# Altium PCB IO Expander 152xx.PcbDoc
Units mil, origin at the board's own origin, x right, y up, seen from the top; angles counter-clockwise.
Board outline 1025 x 2250 mil, 2 copper layers (Top Layer, Bottom Layer), stack 61.811 mil thick; 39 components, 39 nets, 131 pads, 30 vias.
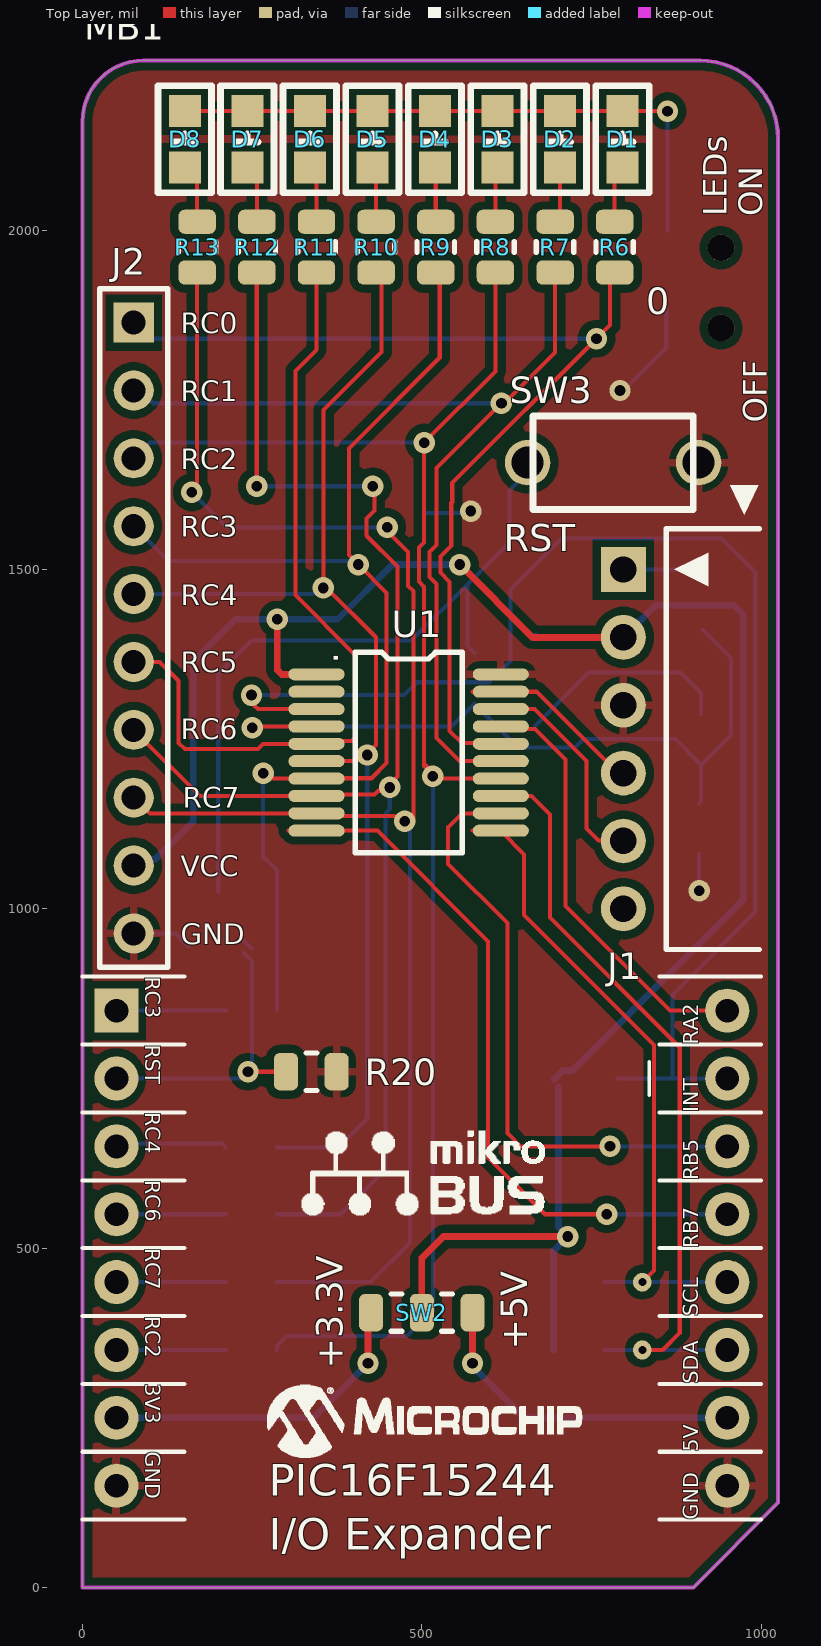
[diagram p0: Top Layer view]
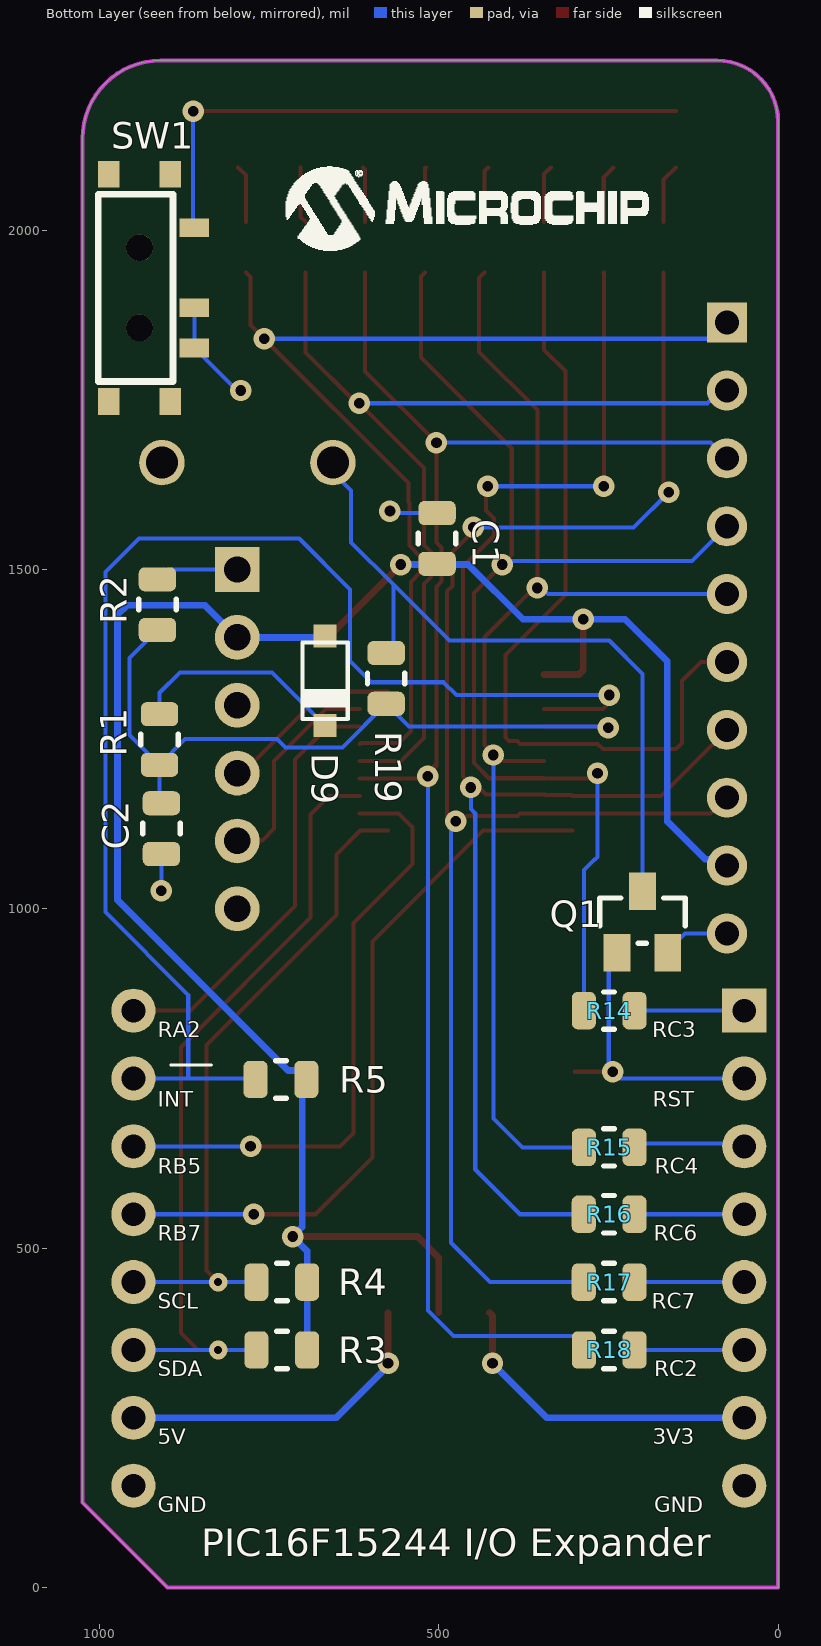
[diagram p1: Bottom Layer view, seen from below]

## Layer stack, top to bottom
Top Solder: solder mask 0.3937, Solder Resist, Dk 3.5
Top Layer: signal copper 1.378
Dielectric1: core 59.0551, FR-4, Dk 4.8
Bottom Layer: signal copper 1.378
Bottom Solder: solder mask 0.3937, Solder Resist, Dk 3.5

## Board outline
0,0 0,2160 cw(c90,2160) 90,2250 910,2250 cw(c910,2135) 1025,2135 1025,125 900,0

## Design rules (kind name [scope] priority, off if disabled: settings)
AcuteAngle [All] p1: minimum=0.00000000000000E+0000 checktracksonly=TRUE
BoardOutlineClearance BoardOutlineClearance_Overlay [OnLayer('Top Overlay','Bottom Overlay')] p1: gap=0 ignorepadtopadclearanceinfootprint=FALSE
BoardOutlineClearance [All] p2: gap=15 ignorepadtopadclearanceinfootprint=FALSE
Clearance "Net to Polygon 0.5mm" [InNet('your net here') vs (IsRegion)] p1: gap=19.68 ignorepadtopadclearanceinfootprint=FALSE
Clearance "Poly 0.3mm" [(IsRegion)] p2: gap=11.81 ignorepadtopadclearanceinfootprint=FALSE
Clearance [All] p3: gap=9.84 ignorepadtopadclearanceinfootprint=TRUE
ComponentClearance ComponentClearance_ignore [HasFootprint('NET_TIE_0.5mm')] p1: gap=0 collisioncheckmode=3 verticalgap=0 showdistances=FALSE
ComponentClearance [All] p2: gap=7.87 collisioncheckmode=3 verticalgap=7.87 showdistances=FALSE
DiffPairsRouting [All] p1: maxlimit=9.84 minlimit=9.84 mostfreqgap=9.84 toplayer_minwidth=9.84 toplayer_maxwidth=9.84 toplayer_prefwidth=9.84 bottomlayer_minwidth=9.84 bottomlayer_maxwidth=9.84 bottomlayer_prefwidth=9.84 maxuncoupledlength=500
FabricationTestPointUsage TestPointUsage [All] p1: valid=0 allowmultiple=FALSE
FabricationTestpoint Testpoint [All] p1: side=3 testpointundercomponent=TRUE minsize=40 maxsize=100 preferedsize=60 minholesize=0 maxholesize=40 preferedholesize=32 testpointgrid=1 allowsidetop=TRUE allowsidebottom=TRUE usegrid=TRUE gridtolerance=0.01
HoleSize [All] p1: absolutevalues=TRUE maxlimit=236.22 minlimit=9.84 maxpercent=80.000 minpercent=20.000
HoleToHoleClearance [All] p1: gap=11.81 allowstackedmicrovias=FALSE
MinimumAnnularRing [All] p1: minimumring=5.91
MinimumSolderMaskSliver [All] p1: minsoldermaskwidth=1
PasteMaskExpansion PasteMaskExpansion_DNP [IsPad AND HasCompParameterValue('Populated','DNP')] p1: expansion=-196.85
PasteMaskExpansion [All] p2: expansion=0
PlaneClearance PlaneClearance_pads [IsPad] p1: clearance=11.81
PlaneClearance PlaneClearance_drill [IsObjectKind('Hole')] p2: clearance=15.75
PlaneConnect PlaneConnect_full [IsVia] p1: planeconnectstyle=Direct reliefexpansion=19.68 reliefentries=4 reliefconductorwidth=11.81 reliefairgap=11.81
PlaneConnect [All] p2: planeconnectstyle=Relief reliefexpansion=11.81 reliefentries=4 reliefconductorwidth=9.84 reliefairgap=9.84
PolygonConnect PolygonConnect_0.7 [IsNamedPolygon('0.7mm') vs (InPadClass('All Pads'))] p1: connectstyle=Relief reliefconductorwidth=27.56 reliefentries=4 polygonreliefangle="90 Angle" airgapwidth=9.84
PolygonConnect PolygonConnect_0.5 [IsNamedPolygon('0.5mm') vs (InPadClass('All Pads'))] p2: connectstyle=Relief reliefconductorwidth=19.68 reliefentries=4 polygonreliefangle="90 Angle" airgapwidth=9.84
PolygonConnect PolygonConnect_full [All vs IsVia or IsNamedPolygon('full')] p3: connectstyle=Direct reliefconductorwidth=0 reliefentries=4 polygonreliefangle="90 Angle" airgapwidth=10
PolygonConnect [All] p4: connectstyle=Relief reliefconductorwidth=11.81 reliefentries=4 polygonreliefangle="90 Angle" airgapwidth=9.84
RoutingCorners [All] p1: cornerstyle=45-Degree minsetback=98.43 maxsetback=98.43
RoutingVias [All] p1: holewidth=15.75 width=31.5 viastyle="Through Hole" minholewidth=11.81 minwidth=27.56 maxholewidth=62.99 maxwidth=98.43
SMDToCorner [All] p1: distance=39370
ShortCircuit [IsNet] p1: allowed=FALSE
SilkToSilkClearance [All] p1: silktosilkclearance=5
SilkToSolderMaskClearance SilkscreenOverComponentPads [IsPad] p1: minsilkscreentomaskgap=3 clearancetoexposedcopper=TRUE
SolderMaskExpansion SolderMaskExpansion_Component_Via [IsComponentVia] p1: expansion=2.95 istentingtop=FALSE soldermaskfromhole=TRUE
SolderMaskExpansion [All] p2: expansion=3.94 istentingtop=FALSE
UnRoutedNet [All] p1: checkbadconnections=TRUE
ViasUnderSMD [All] p1: allowed=FALSE
Width [All] p1: maxlimit=10 minlimit=6 preferedwidth=6 minimp=50.000000 maximp=50.000000 favimp=50.000000
15 further rules are at their usual default settings.

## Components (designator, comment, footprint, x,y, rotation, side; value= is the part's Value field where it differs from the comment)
C1 "Capacitor NP" RES_C_0805 502.52,1545.77 r270 bottom value=0.1uF
C2 "Capacitor NP" RES_C_0805 908.71,1118.16 r90 bottom value=10nF
D1 "LED" "0805 LED Package" 795.59,2133.94 r90 top
D2 "LED" "0805 LED Package" 703.48,2133.94 r90 top
D3 "LED" "0805 LED Package" 611.36,2133.94 r90 top
D4 "LED" "0805 LED Package" 519.25,2133.94 r90 top
D5 "LED" "0805 LED Package" 427.14,2133.94 r90 top
D6 "LED" "0805 LED Package" 335.03,2133.94 r90 top
D7 "LED" "0805 LED Package" 242.92,2133.94 r90 top
D8 "LED" "0805 LED Package" 150.81,2133.94 r90 top
D9 "SD101BW-E3-08" SOD123 667.62,1336.09 r270 bottom
J1 "Header 1x6" HDR_F_2.54_1x6_RA 797,1250 r270 top locked value="HDR-2.54 Female 1x6"
J2 "Header 10" HDR1X10 75.49,1863.74 r270 top (schematic designator P?)
MB1 "mikroBUS" "mikroBUS - Large" 0,0 r0 top locked
Q1 "Transistor MOS-N GSD" SOT-23-3 200,980.61 r180 bottom value=2N7002
R1 "Resistor" RES_C_0805 911.5,1249.54 r90 bottom value=10k
R2 "Resistor" RES_C_0805 914.54,1448.18 r90 bottom value=470R
R3 "Resistor" RES_C_0805 731.31,350 r180 bottom value=DNP
R4 "Resistor" RES_C_0805 731.31,450 r180 bottom value=DNP
R5 "Resistor" RES_C_0805 732.63,748.6 r180 bottom value=10k
R6 "Resistor" RES_C_0805 784.19,1975 r90 top value=1k
R7 "Resistor" RES_C_0805 696.31,1975 r90 top value=1k
R8 "Resistor" RES_C_0805 608.43,1975 r90 top value=1k
R9 "Resistor" RES_C_0805 520.55,1975 r90 top value=1k
R10 "Resistor" RES_C_0805 432.67,1975 r270 top value=1k
R11 "Resistor" RES_C_0805 344.79,1975 r270 top value=1k
R12 "Resistor" RES_C_0805 256.91,1975 r270 top value=1k
R13 "Resistor" RES_C_0805 169.03,1975 r270 top value=1k
R14 "Resistor" RES_C_0805 248.95,850 r0 bottom value=DNP
R15 "Resistor" RES_C_0805 248.95,648.62 r0 bottom value=DNP
R16 "Resistor" RES_C_0805 249,550 r0 bottom value=DNP
R17 "Resistor" RES_C_0805 249,450 r0 bottom value=DNP
R18 "Resistor" RES_C_0805 248.95,350 r0 bottom value=DNP
R19 "Resistor" RES_C_0805 577.47,1339.57 r90 bottom value=1k
R20 "Resistor" RES_C_0805 337.21,760 r180 top value=10k
SW1 "SWITCH SLIDE 3 Pin SPDT" PCBComponent_1 940.85,1915 r90 bottom locked
SW2 "SMD Power Select" "3-Pad Select 0805" 462.6,405 r0 top
SW3 "SPST Switch" PTS636 781.97,1657.41 r0 top
U1 "PIC16F15244" SSOP-20_P0.65 480.62,1230.32 r0 top locked

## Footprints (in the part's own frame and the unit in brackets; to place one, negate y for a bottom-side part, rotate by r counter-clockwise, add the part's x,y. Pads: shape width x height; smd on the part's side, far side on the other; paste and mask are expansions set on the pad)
"3-Pad Select 0805" [mm] "Chip Resistor, 2-Leads, Body 2.0x1.3mm, IPC Medium Density"
  rrect50% 0.9x1.4 smd: 1(-0.95,0) 2(0.95,0) 3(2.85,0)
  silkscreen extent -0.2,-0.7 2.1,0.7, body extent -1,-0.63 2.6,0.63, height 0.78
"0805 LED Package" [mm] "0805 Package for LED"
  rect 1.2x1.2 smd: Anode(-1.05,0) Cathode(1.05,0)
  silkscreen extent -2,-1 2,1
HDR1X10 [mm] "Connector; Header; 10 Position"
  rect 1.5x1.5 hole 0.9: 1(0,0)
  round 1.5 hole 0.9: 2(2.54,0) 3(5.08,0) 4(7.62,0) 5(10.16,0) 6(12.7,0) 7(15.24,0) 8(17.78,0) 9(20.32,0) 10(22.86,0)
  silkscreen extent -1.27,-1.27 24.13,1.27
HDR_F_2.54_1x6_RA [mil] "Header Female Right Angle 6 Way 2.54mm Pitch"
  rect 66x66 hole 39: 1(-250,0)
  round 66 hole 39: 2(-150,0) 3(-50,0) 4(50,0) 5(150,0) 6(250,0)
  silkscreen extent -310,63 310,200, body extent -310,-8 310,395, height 97
"mikroBUS - Large" [mil]
  rect 65x65 hole 35: 1(50,850)
  round 65 hole 35: 2(50,750) 3(50,650) 4(50,550) 5(50,450) 6(50,350) 7(50,250) 8(50,150) 9(950,150) 10(950,250) 11(950,350) 12(950,450) 13(950,550) 14(950,650) 15(950,750) 16(950,850)
  Keep-Out Layer lines w6: 910,2250 90,2250 ccw(c90,2160) 0,2160 0,0 900,0 1025,125 1025,2135
  silkscreen extent 0,100 1000,900, body extent -5,100 1010,900, height 82
PCBComponent_1 [mm]
  rect 0.7x1.1 smd: 1(2.25,-2.05) 2(-0.75,-2.05) 3(-2.25,-2.05)
  round 1 hole 1 unplated: MECH-1(-1.5,0) MECH-2(1.5,0)
  rect 1x0.8 smd: MECH-3(4.25,1.15) MECH-4(4.25,-1.15) MECH-5(-4.25,-1.15) MECH-6(-4.25,1.15)
  silkscreen extent -3.5,-1.25 3.5,1.55
PTS636 [mil] "PTS636 TH Switch, 6mm x 3.5mm, 4.5mm Tall"
  round 67 hole 47.24: 1(-125.98,0) 2(125.98,0)
  silkscreen extent -118,-69 118,69
RES_C_0805 [mm] "Chip Resistor, 2-Leads, Body 2.0x1.3mm, IPC Medium Density"
  rrect50% 0.9x1.4 smd: 1(-0.95,0) 2(0.95,0)
  silkscreen extent -0.2,-0.7 0.2,0.7, body extent -1,-0.63 1,0.63, height 0.78
SOD123 [mm]
  rect 0.85x0.85 smd: ANODE(-1.675,0) CATHODE(1.675,0)
  silkscreen extent -1.43,-0.85 1.43,0.85
SOT-23-3 [mm]
  rect 1x1.4 smd: 1(-0.95,-1.15) 2(0.95,-1.15) 3(0,1.15)
  silkscreen extent -1.6,-0.8 1.6,0.9, body extent -1.5,-1.25 1.5,1.25, height 1.09
SSOP-20_P0.65 [mm] "SOP, 20-Leads, Body 7.5x5.6mm (max), Pitch 0.65mm, IPC Medium Density"
  oval 2.1x0.45 smd mask+0.05: 1(-3.45,2.925) 2(-3.45,2.275) 3(-3.45,1.625) 4(-3.45,0.975) 5(-3.45,0.325) 6(-3.45,-0.325) 7(-3.45,-0.975) 8(-3.45,-1.625) 9(-3.45,-2.275) 10(-3.45,-2.925) 11(3.45,-2.925) 12(3.45,-2.275) 13(3.45,-1.625) 14(3.45,-0.975) 15(3.45,-0.325) 16(3.45,0.325) 17(3.45,0.975) 18(3.45,1.625) 19(3.45,2.275) 20(3.45,2.925)
  silkscreen extent -2,-3.75 2,3.75, body extent -3.95,-3.65 3.95,3.67, height 1.95

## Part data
C1 C2: library part CAP2000, Package=0805, Voltage=10V
D9: library part SC_Diode, "Schottky Diode"
J1: library part CON0170, Current=3A, Manufacturer 1=Sullins, Manufacturer 2=Mill-Max, Manufacturer 3="SHENZHEN JUNHAO ENGINEERING", Manufacturer 4=Samtec, Manufacturer Part Number 1=PPPC061LGBN-RC, Manufacturer Part Number 2=801-43-006-20-001000, Manufacturer Part Number 3=R-212-0620-0021-000, Manufacturer Part Number 4=SSW-106-02-F-S-RA, Supplier Part Number 1=S5481-ND
J2: "Header, 10-Pin"
MB1: library part "mikroBUS compatible add-on board", "mikroBUS compatible add-on board"
Q1: library part TRA1102, "Transistor MOS", Current=170mA, Drain to Source Voltage=60V, Gate to Source Voltage=20V, Manufacturer 1="Diodes Inc", Manufacturer Part Number 1=2N7002-7-F, Operating Temperature="-55C to +150C", Package=SOT-23-3, Power=370mW, Supplier Part Number 1=2N7002-FDICT-ND
R1 R20: library part RSMT0027, Package=0805, Tolerance=5%
R2 R6 R7 R8 R9 R10 R11 R12 R13 R14 R15 R16 R17 R18 R19: library part RSMT0097, Package=0805, Tolerance=5%
R3 R4 R5: library part RSMT0097, Package=0805, Tolerance=5%, Voltage=150V
SW2: library part "SWITCH SLIDE 3 Pin SPDT"
SW3: library part SPST
U1: library part "PIC16F1524X SOIC-20_SSOP-20_PDIP-20", "PIC16F1524X SOIC-20_SSOP-20_PDIP-20"

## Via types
v1: diameter 31.5, hole 15.75, Top Layer to Bottom Layer, 28 vias
v2: diameter 27.56, hole 11.81, Top Layer to Bottom Layer, 2 vias

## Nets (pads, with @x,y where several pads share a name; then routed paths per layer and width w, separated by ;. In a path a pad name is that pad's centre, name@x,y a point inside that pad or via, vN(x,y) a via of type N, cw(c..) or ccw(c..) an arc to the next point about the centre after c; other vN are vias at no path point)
+3.3: MB1.7 SW2.1 | length 480.6
  Top Layer w10: v1(420.78,330.32) 420.78,400.59 SW2.1
  Bottom Layer w10: MB1.7 340.47,250 v1(420.78,330.32)
+5: MB1.10 SW2.3 | length 492.6
  Top Layer w10: v1(574.73,330.32) 574.8,330.39 SW2.3 ; MB1.10@945,255 MB1.10
  Bottom Layer w10: v1(574.73,330.32) 574.73,326.48 651.2,250 MB1.10
\I\N\T\: MB1.15 R5.1 U1.3 | length 1990
  Top Layer w6: v1(248.95,1314.96) 253.83,1310.08 253.83,1298.77 258.31,1294.29 U1.3
  Bottom Layer w6: v1(248.95,1314.96) 474.02,1314.96 492.9,1333.83 599.29,1333.83 630.51,1365.05 630.51,1470.77 705.58,1545.84 941.9,1545.84 991.29,1496.45 991.29,995.43 869.2,873.34 869.2,750 ; 788.4,750 869.2,750 ; MB1.15 869.2,750
GND: C1.1 C2.1 J1.3 J2.10 MB1.8 MB1.9 Q1.2 R20.1 SW1.2 SW1.3 SW3.2 U1.20 | length 383.5
  Bottom Layer w6: J2.10 137.23,963.74 Q1.2@156.24,944.72 ; C1.1 569.11,1583.18 v1(571.99,1586.06) ; v1(792,1763.74) 797.46,1763.74 SW1.3 SW1.2 ; J1.3 J1.3@808.26,1288.74 ; v1@908.17,1025.89 v1(908.71,1026.42) C2.1
ICSPCLK: J1.5 U1.18 | length 319.4
  Top Layer w6: U1.18 666.28,1294.29 742.85,1217.73 742.85,1118.16 760.06,1100.94 796.06,1100.94 J1.5
ICSPDAT: J1.4 U1.19 | length 286.8
  Top Layer w6: 575.02,1319.88 U1.19 669.13,1319.88 789.01,1200 J1.4 J1.4@786.25,1210.75
NetC2_2: C2.2 R1.1 R2.1 R19.1 U1.4 | length 1126
  Top Layer w6: v1(250.27,1266.86) 252.11,1268.7 U1.4
  Bottom Layer w6: v1@242.27,1271.74 v1@250.27,1263.74 ; v1(250.27,1266.86) v1@250.27,1263.74 ; C2.2 911.5,1158.36 R1.1 ; R2.1 955.61,1369.72 955.61,1256.24 R1.1 ; v1@250.27,1263.74 255.25,1268.72 362.88,1268.72 544.02,1268.72 R19.1 641.97,1237.66 725.79,1237.66 738.13,1250 873.64,1250 R1.1
NetD1_Anode: D1.Anode R6.2 | length 84.9
  Top Layer w6: R6.2 784.19,2081.2 D1.Anode
NetD1_Cathode: D1.Cathode D2.Cathode D3.Cathode D4.Cathode D5.Cathode D6.Cathode D7.Cathode D8.Cathode SW1.1 | length 886.9
  Top Layer w6: D8.Cathode D7.Cathode D6.Cathode D5.Cathode D4.Cathode D3.Cathode D2.Cathode D1.Cathode v1(862,2175.28)
  Bottom Layer w6: SW1.1@862,1999.59 v1(862,2175.28)
NetD2_Anode: D2.Anode R7.2 | length 83.2
  Top Layer w6: R7.2 703.48,2019.57 D2.Anode
NetD3_Anode: D3.Anode R8.2 | length 81.4
  Top Layer w6: R8.2 608.43,2089.66 D3.Anode
NetD4_Anode: D4.Anode R9.2 | length 80.7
  Top Layer w6: D4.Anode 520.55,2091.3 R9.2
NetD5_Anode: D5.Anode R10.1 | length 82.5
  Top Layer w6: D5.Anode 432.67,2087.07 R10.1
NetD6_Anode: D6.Anode R11.1 | length 84.2
  Top Layer w6: D6.Anode 344.79,2082.84 R11.1
NetD7_Anode: D7.Anode R12.1 | length 86
  Top Layer w6: D7.Anode 256.91,2078.61 R12.1
NetD8_Anode: D8.Anode R13.1 | length 87.7
  Top Layer w6: D8.Anode 169.03,2074.37 R13.1
NetD9_Cathode: D9.CATHODE R1.2 | length 320.2
  Bottom Layer w6: D9.CATHODE 745.91,1348.43 881.46,1348.43 911.5,1318.38 R1.2
NetMB1_1: MB1.1 R14.1 | length 161.6
  Bottom Layer w6: MB1.1 R14.1
NetMB1_3: MB1.3 R15.1 | length 165.8
  Bottom Layer w6: MB1.3 54.38,654.38 205.79,654.38 R15.1
NetMB1_4: MB1.4 R16.1 | length 161.6
  Bottom Layer w6: MB1.4 R16.1
NetMB1_5: MB1.5 R17.1 | length 161.6
  Bottom Layer w6: MB1.5 R17.1
NetMB1_6: MB1.6 R18.1 | length 161.6
  Bottom Layer w6: MB1.6 R18.1
NetQ1_3: Q1.3 R19.2 SW3.1 | length 1063.5
  Bottom Layer w6: Q1.3 200,1346.23 248.83,1395.06 484.24,1395.06 566.99,1477.81 ; R19.2 566.99,1387.45 566.99,1477.81 ; SW3.1 655.98,1643.13 629.14,1616.28 629.14,1539.96 566.99,1477.81
RA2: MB1.16 U1.17 | length 633.4
  Top Layer w6: U1.17 652.09,1268.7 655.98,1264.81 666.55,1264.81 711.63,1219.73 711.63,1003.96 865.59,850 MB1.16
RB5: MB1.14 U1.12 | length 905.2
  Top Layer w6: U1.12 559.36,1140.75 538.77,1120.16 538.77,1066.02 625.97,978.82 625.97,669.37 645.34,650 v1(777.32,650)
  Bottom Layer w6: v1(777.32,650) MB1.14
RB7: MB1.13 U1.10 | length 1067.2
  Top Layer w6: 303.37,1115.16 U1.10 434.72,1115.16 597.78,952.1 597.78,633.82 681.59,550 v1(772.67,550)
  Bottom Layer w6: v1(772.67,550) MB1.13
RC0: J2.1 R6.1 U1.16 | length 1562.5
  Top Layer w6: U1.16 615.5,1244.06 558.91,1244.06 541.08,1261.88 541.08,1481.71 527.39,1495.4 527.39,1519.08 543.4,1535.09 543.4,1597.91 544.8,1599.3 544.8,1627.48 v1(757.32,1840) 777.32,1860 777.32,1930.72 R6.1
  Bottom Layer w6: J2.1 99.23,1840 v1(757.32,1840)
RC1: J2.2 R7.1 U1.15 | length 1427.6
  Top Layer w6: U1.15 616.36,1217.6 555.79,1217.6 521.77,1251.61 521.77,1478.61 511.55,1488.84 511.55,1525.65 521.77,1535.87 521.77,1649.49 v1(617.28,1745) 621.62,1745 696.31,1819.69 R7.1
  Bottom Layer w6: J2.2 85.35,1763.74 104.08,1745 v1(617.28,1745)
RC2: J2.3 R8.1 R18.2 U1.14 | length 2401.9
  Top Layer w6: 503.45,1214.41 503.45,1210.43 516.2,1197.68 v1(516.2,1195.34) ; 503.45,1474.53 495.71,1482.27 495.71,1532.21 503.5,1540 v1(503.5,1686.91) 608.43,1791.83 R8.1 ; 503.5,1474.48 503.5,1214.41 525.98,1191.93 U1.14
  Bottom Layer w6: J2.3 76.48,1663.74 99.65,1686.91 v1(503.5,1686.91) ; R18.2 286.36,356.25 300.63,370.52 478.37,370.52 516.2,408.36 v1(516.2,1195.34)
RC3: J2.4 R9.1 R14.2 U1.7 | length 1711.6
  Top Layer w6: v1(266.19,1200) 273.09,1200 281.15,1191.94 U1.7 ; U1.7@344.79,1192.41 425.86,1192.41 448.18,1214.73 448.18,1465.55 v1(406.49,1507.24) 392.49,1521.24 392.49,1678.17 526.4,1812.08 526.4,1931.75 R9.1
  Bottom Layer w6: J2.4 126.73,1512.5 395.37,1512.5 400.63,1507.24 v1(406.49,1507.24) ; v1(266.19,1200) 266.19,1076.35 269.7,1072.83 270.48,1072.83 286.36,1056.95 R14.2
RC4: J2.5 R10.2 R15.2 U1.6 | length 1837.9
  Top Layer w6: U1.6 403.63,1217.52 412.69,1226.58 v1(419.59,1226.58) 419.59,1228.92 432.34,1241.67 432.34,1400.15 359.65,1472.83 v1(354.87,1472.83) 354.87,1734.76 440.71,1820.6 440.71,1929.56 R10.2
  Bottom Layer w6: J2.5 338.87,1463.74 347.97,1472.83 v1(354.87,1472.83) ; R15.2 376.85,648.62 419.59,691.36 v1(419.59,1226.58)
RC5: J2.6 R11.2 U1.5 | length 1174.9
  Top Layer w6: J2.6 113.82,1363.74 141.47,1336.09 141.47,1244.57 150.81,1235.24 258.31,1235.24 266.19,1243.11 U1.5 380.44,1243.11 384.33,1247 396.3,1247 401.88,1252.58 401.88,1374.28 313.57,1462.59 313.57,1792.53 344.79,1823.75 R11.2
RC6: J2.7 R12.2 R16.2 U1.8 | length 2134.8
  Top Layer w6: J2.7 172.89,1166.34 303.37,1166.34 304.87,1167.85 342.92,1167.85 343.38,1168.31 430.32,1168.31 436.04,1174.04 447.91,1174.04 v1(452.79,1178.91) ; v1(256.83,1622.61) 256.83,1937.52 R12.2 ; v1(427.82,1622.61) 430.42,1620.01 430.42,1586.9 418.52,1575.01 418.52,1549.73 464.02,1504.23 464.02,1195.18 452.79,1183.95 v1@452.79,1179.07
  Bottom Layer w6: v1(256.83,1622.61) v1(427.82,1622.61) ; R16.2 380.36,550 446.27,615.92 446.27,1140.71 452.79,1147.23 v1(452.79,1178.91)
RC7: J2.8 R13.2 R17.2 U1.9 | length 2356.9
  Top Layer w6: J2.8 76.84,1163.74 99.83,1140.75 U1.9 380.44,1140.75 384.33,1136.86 459.97,1136.86 467.96,1128.87 v1(474.86,1128.87) 487.61,1128.87 487.61,1467.97 479.86,1475.71 479.86,1525.77 449.03,1556.6 v1(449.03,1562.37) ; v1(161.15,1613.62) 161.15,1619.48 169.03,1627.36 R13.2
  Bottom Layer w6: v1(161.15,1613.62) 213.18,1561.59 448.26,1561.59 v1(449.03,1562.37) ; R17.2 424.28,450 482.28,508 482.28,1114.55 474.86,1121.97 v1(474.86,1128.87)
RST: MB1.2 Q1.1 R20.2 | length 452.2
  Top Layer w6: v1(243.88,760) R20.2
  Bottom Layer w6: MB1.2 233.88,750 v1(243.88,760) 249.54,765.66 249.54,923.2 Q1.1 ; Q1.1@237.94,952.6 Q1.1@248.95,941.59
SCL: MB1.12 R4.1 U1.11 | length 987.9
  Top Layer w6: 575.02,1115.16 615.72,1115.16 650.62,1080.26 650.62,990.7 842,799.31 842,467 v2(825,450)
  Bottom Layer w6: R4.1 v2(825,450) MB1.12
SDA: MB1.11 R3.1 U1.13 | length 1173.8
  Top Layer w6: U1.13 661.89,1166.34 688.96,1139.27 688.96,987.09 880,796.05 880,375 855,350 v2(825,350)
  Bottom Layer w6: R3.1 v2(825,350) MB1.11
VCC: C1.2 D9.ANODE J1.2 J2.9 R3.2 R4.2 R5.2 SW2.2 U1.1 | length 3073.9
  Top Layer w10: v1(287.08,1426.69) 287.08,1352 293.61,1345.47 U1.1 ; SW2.2 500,485.43 531.65,517.08 v1(715,517.08) ; v1(555.98,1507.24) 663.22,1400 J1.2
  Bottom Layer w10: J2.9 84.91,1073.15 107.58,1073.15 163.22,1128.8 163.22,1364.37 225.54,1426.69 292.9,1426.69 376.15,1426.69 456.7,1507.24 v1(555.98,1507.24) ; D9.ANODE 669.66,1400 J1.2 844.24,1447.24 959.63,1447.24 973.45,1433.42 973.45,1013.09 722.09,761.73 707.65,761.73 695.23,749.31 R5.2 ; R3.2 R4.2 693.91,495.99 v1(715,517.08) 715,517.51 701.29,531.21 R5.2@701.29,737.7
VPP/\M\C\L\R\: J1.1 R2.2 | length 142.4
  Bottom Layer w6: J1.1@783.61,1486.61 J1.1 900.12,1500 R2.2
pads on no net: J1.6 SW1.MECH-1 SW1.MECH-2 SW1.MECH-3 SW1.MECH-4 SW1.MECH-5 SW1.MECH-6 U1.2

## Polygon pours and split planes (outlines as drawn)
GND on Top Layer "GND_L01_P002" (solid, remove dead copper, pour order 2): 1000,300 1000,0 0,0 0,300
GND on Top Layer "GND_L01_P004" (solid, remove dead copper, pour order 4): 0,0 416.11,0 416.11,2248.11 418,2250 0,2250
GND on Top Layer "GND_L01_P007" (solid, remove dead copper, pour order 7): -5,2249.05 -5,5 0,0 1030,0 1030,2249.05
no net on Top Overlay "NONET_L-01_P-001" (solid): 954.68,1623.91 995.46,1623.91 974.88,1580.61

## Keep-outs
Keep-Out Layer:
  lines w6: 910,2250 cw(c910,2135) 1025,2135 ; 1555,4120 cw(c1555,4005) 1670,4005
  text "'.Layer_Name'" at 11841.34,-6245 h59.06

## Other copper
Top Layer:
  text "'.ProjectRevisionART'" at 13226.29,-6238 h59.06
  text "'.Layer_Name'" at 11841.34,-6245 h59.06
Bottom Layer:
  text "04-'.ProjectPCBNumber'-R'.ProjectRevisionART'" at 9527.56,-4271.65 h47.24
  text "'.ProjectRevisionART'" at 13226.29,-6238 h59.06
  text ".ProjectRevisionART" at 13226.29,-6238 h59.06
  text ".ProjectRevisionART" at 13226.29,-6238 h59.06
  text "'.Layer_Name'" at 11841.34,-6245 h59.06

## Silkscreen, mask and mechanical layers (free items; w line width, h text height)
Top Overlay:
  drawing of 26 lines, arcs and shapes, not listed
  text "LEDs  / ON" at 1001.88,2020.68 h35 r90
  text "0" at 831.02,1876.41 h39.37
  text "RC0" at 144.88,1847.87 h30
  text "RC1" at 144.88,1747.87 h30
  text "OFF" at 1008.06,1716.18 h35 r90
  text "RC2" at 144.88,1647.87 h30
  text "RC3" at 144.88,1547.93 h30
  text "RST" at 621,1526.96 h40
  text "RC4" at 144.88,1447.24 h30
  text "RC5" at 144.88,1348.43 h30
  text "RC6" at 144.88,1249.54 h30
  text "RC7" at 147.78,1148.62 h30
  text "VCC" at 145.1,1048.05 h30
  text "GND" at 145.1,947.87 h30
  text "+5V" at 655.58,350 h39.37 r90
  text "+3.3V" at 383.33,322.44 h39.37 r90
  text "C" at 10216.54,-4421.16 h314.96
  text "'.ProjectPartNumber'" at 9114.17,-4448.82 h47.24
  text "" at 9940.94,-4472.46 h314.96
  text "5" at 10964.57,-4495.81 h314.96
  text "7" at 11358.27,-4495.81 h314.96
  text "0" at 11751.97,-4495.81 h314.96
  text "1" at 12145.67,-4495.81 h314.96
  text "6" at 10570.87,-4497.12 h314.96
  text "2" at 12539.37,-4497.12 h314.96
  text "3" at 12933.07,-4497.12 h314.96
  text "4" at 13329.9,-4497.12 h314.96
  text "ICD" at 11196.85,-4803.15 h60
  text "M" at 10314.96,-5059.05 h393.7
  text "" at 12401.58,-5077.11 h393.7
  text "" at 11574.8,-5078.1 h393.7
  text "" at 12007.87,-5078.1 h393.7
  text "" at 12755.91,-5078.1 h393.7
  text "" at 13188.98,-5078.1 h393.7
  text "" at 13622.05,-5084.99 h393.7
  text "*h" at 8964.57,-5118.11 h275.59
  text "" at 11259.84,-5196.85 h393.7
  text "dsPICDEM.net™" at 7312.99,-5462.6 h118.11
  text "mTouch®" at 8188.98,-5462.6 h118.11
  text "chipKIT™" at 8750,-5462.6 h118.11
  text "dsPICDEM™" at 7303.15,-5688.98 h118.11
  text "MPLAB®" at 8188.98,-5708.66 h118.11
  text "dsPIC®" at 8750,-5708.66 h118.11
  text "PICDEM.net™" at 7303.15,-5935.04 h118.11
  text "PICkit™" at 8198.82,-5944.88 h118.11
  text "PIC®" at 8750,-5944.88 h118.11
  text "PICDEM™" at 7303.15,-6190.94 h118.11
  text "PICtail™" at 8198.82,-6190.94 h118.11
  text "'.ProjectRevisionART'" at 13226.29,-6238 h59.06
  text "'.Layer_Name'" at 11841.34,-6245 h59.06
Bottom Overlay:
  drawing of 15 lines, arcs and shapes, not listed
  text "PIC16F15244 I/O Expander" at 850,32.44 h70
  text "'.ProjectRevisionART'" at 13226.29,-6238 h59.06
  text "'.Layer_Name'" at 11841.34,-6245 h59.06
Top Paste:
  text "'.ProjectRevisionART'" at 13226.29,-6238 h59.06
  text "'.Layer_Name'" at 11841.34,-6245 h59.06
Bottom Paste:
  text "'.ProjectRevisionART'" at 13226.29,-6238 h59.06
  text "'.Layer_Name'" at 11841.34,-6245 h59.06
Top Solder:
  text "'.ProjectRevisionART'" at 13226.29,-6238 h59.06
  text "'.Layer_Name'" at 11841.34,-6245 h59.06
Bottom Solder:
  text "'.ProjectRevisionART'" at 13226.29,-6238 h59.06
  text "'.Layer_Name'" at 11841.34,-6245 h59.06
NOTES (M1):
  text "ASSEMBLY NOTES:" at 1157.48,-4295.28 h157.48
  text "1. ALL COMPONENTS SHALL BE RoHS COMPLIANT." at -185.04,-4496.06 h118.11
  text "2. ALL UNUSED THROUGH HOLE COMPONENT LOCATIONS SHALL BE FREE OF SOLDER." at -185.04,-4614.17 h118.11
  text "3. ALL COMPONENTS SHALL BE MOUNTED FLUSH TO THE BOARD, EXCEPT AS NOTED." at -185.04,-4732.28 h118.11
  text "4. FINISHED BOARD SHALL BE FREE OF ALL RESIDUES." at -185.04,-4850.39 h118.11
  text "5. ALL LEADS SHALL BE TRIMMED TO A MAXIMUM HEIGHT OF 2mm" at -185.04,-4968.5 h118.11
  text "'.Layer_Name'" at 12550,-6245 h59.06
BOARD (M2):
  lines w6: 85.57,2250 910,2250 cw(c910,2135) 1025,2135 1025,125 900,0 0,0 ; 90,2250 ccw(c90,2160) 0,2160 0,0 ; 0,0 0,0
REF POINTS (M3):
  text "'.Layer_Name'" at 11841.34,-6245 h59.06
FAB (M4):
  drawing of 284 lines, arcs and shapes, not listed
  text "THIS PCB TO BE MANUFACTURED TO MEET ALL ACCEPTANCE LEVELS" at 9330.28,2033.94 h70
  text "OF A CLASS 2 PCB PER ANSI/IPC-A-600G." at 9330.28,1883.94 h70
  text "MATERIAL:" at 9330.28,1702.05 h70
  text "FR-4 or Equivalent" at 10130.28,1702.05 h70
  text "CONTROLLED IMPEDANCE" at 12342.52,1535.43 h70
  text "MULTILAYER" at 10355.28,1530.79 h70
  text "2" at 11280.28,1530.79 h70
  text "LAYERS" at 11455.28,1530.79 h70
  text "Cu WEIGHT EXTERNAL LAYERS" at 10130.28,1339.84 h70
  text "35um" at 12180.28,1339.84 h70
  text "FINISHED" at 12555.28,1339.84 h70
  text "Cu WEIGHT INTERNAL LAYERS" at 10130.28,1148.9 h70
  text "N/A" at 12180.28,1148.9 h70
  text "FINISHED" at 12555.28,1148.9 h70
  text "FINISHED OVERALL THICKNESS" at 10130.28,957.95 h70
  text "1.6" at 12230.28,957.95 h70
  text "mm" at 12555.28,957.95 h70
  text "10" at 13130.28,957.95 h70
  text "%" at 13455.28,957.95 h70
  text "COPPER THIEVING ALLOWED" at 10137.8,767.72 h70
  text "YES" at 12381.89,767.72 h70
  text "NO" at 13051.18,767.72 h70
  text "X" at 12838.23,748.03 h102.36
  text "FINISH:" at 9330.71,590.55 h70
  text "LEAD-FREE HOT AIR LEVELING" at 10354.33,578.74 h70
  text "X" at 10173.23,551.18 h102.36
  text "IMMERSION GOLD" at 10355.28,360.71 h70
  text "IMMERSION TIN" at 10355.28,144.17 h70
  text "SMOBC WITH SELECTIVE GOLD PLATING ON LANDS" at 10355.28,-1.69 h70
  text "INDICATED. 1um GOLD OVER 5-10 um NICKEL" at 10355.28,-151.69 h70
  text "SOLDERMASK" at 10130.28,-361.73 h70
  text "DYNACHEM EPIC 200 LPI OR EQUIVALENT" at 10980.28,-361.73 h70
  text "SOLDERMASK COLOR" at 10130.28,-611.73 h70
  text "GREEN HIGH GLOSS" at 11380.28,-611.73 h70
  text "SILKSCREEN COLOR" at 10130.28,-861.73 h70
  text "WHITE" at 11380.28,-861.73 h70
  text "Blind / Burried Vias" at 10374.02,-1102.36 h70
  text "DRILLING:" at 9350.39,-1112.2 h70
  text "Via Layer Pairs" at 10157.48,-1289.37 h70
  text "Top-Bottom" at 10974.41,-1289.37 h70
  text "ALL HOLES TO BE LOCATED BY THE COORDINATES FROM THE NC DRILL DATA PROVIDED." at 9330.28,-1496.06 h70
  text "05-'.ProjectPCBNumber'" at 10590.55,-1751.97 h70
  text "PCB REV" at 12007.87,-1751.97 h70
  text "USE ARTWORK SET NO." at 9330.28,-1755.43 h70
  text "'.ProjectRevisionART'" at 12525.59,-1761.81 h70
  text "ALL UL LOGO, MANUFACTURER'S ID, AND DATE CODES SHALL BE PLACED" at 9330.28,-2005.43 h70
  text "ON THE BOTTOM SIDE UNLESS OTHERWISE INDICATED." at 9330.28,-2155.43 h70
  text "ANY ALTERNATIVES TO THE ABOVE SPECIFICATIONS MUST FIRST BE APPROVED." at 9311.02,-2362.2 h70
  text "Layer" at 8820.04,-2624.99 h60
  text "Name" at 9229.96,-2624.99 h60
  text "Material" at 10159.7,-2624.99 h60
  text "Thickness" at 11019.47,-2624.99 h60
  text "Constant" at 11669.3,-2624.99 h60
  text "Gerber" at 12239.16,-2624.99 h60
  text "Board Layer Stack" at 12709.06,-2624.99 h60
  text "Top Overlay" at 9229.96,-2744.99 h60
  text "GTO" at 12239.16,-2744.99 h60
  text "Top Solder" at 9229.96,-2864.99 h60
  text "Solder Resist" at 10159.7,-2864.99 h60
  text "0.010mm" at 11019.47,-2864.99 h60
  text "3.5" at 11669.3,-2864.99 h60
  text "GTS" at 12239.16,-2864.99 h60
  text "1" at 8820.04,-2984.99 h60
  text "Top Layer" at 9229.96,-2984.99 h60
  text "0.035mm" at 11019.47,-2984.99 h60
  text "GTL" at 12239.16,-2984.99 h60
  text "Dielectric1" at 9229.96,-3104.99 h60
  text "FR-4" at 10159.7,-3104.99 h60
  text "1.500mm" at 11019.47,-3104.99 h60
  text "4.8" at 11669.3,-3104.99 h60
  text "2" at 8820.04,-3224.99 h60
  text "Bottom Layer" at 9229.96,-3224.99 h60
  text "0.035mm" at 11019.47,-3224.99 h60
  text "GBL" at 12239.16,-3224.99 h60
  text "Bottom Solder" at 9229.96,-3344.99 h60
  text "Solder Resist" at 10159.7,-3344.99 h60
  text "0.010mm" at 11019.47,-3344.99 h60
  text "3.5" at 11669.3,-3344.99 h60
  text "GBS" at 12239.16,-3344.99 h60
  text "Bottom Overlay" at 9229.96,-3464.99 h60
  text "GBO" at 12239.16,-3464.99 h60
  text "Total board thickness:" at 8820.04,-3584.99 h60
  text "1.590mm" at 11019.47,-3584.99 h60
  text "'.ProjectRevisionFAB'" at 13226.29,-6238 h59.06
  text "'.Layer_Name'" at 11841.34,-6245 h59.06
Case (M5):
  text "'.Layer_Name'" at 11841.34,-6245 h59.06
Cover (M6):
  text "'.Layer_Name'" at 11841.34,-6245 h59.06
Terminal Block (M7):
  text "'.Layer_Name'" at 11841.34,-6245 h59.06
Route Tool Path:
  text "'.Layer_Name'" at 11841.34,-6245 h59.06
V-Cut (M9):
  text "'.Layer_Name'" at 11841.34,-6245 h59.06
Bottom Assembly:
  text "'.VariantName'" at 1971.26,-5620.08 h35.43
  text "ASSEMBLY VARIANT:" at 2532.28,-5620.08 h35.43
  text "DOCUMENT NUMBER:" at 710.63,-5944.88 h45
  text "02-'.ProjectPCBAssyNumber'-D" at 700.79,-6062.99 h62.99
  text "'.ProjectRevisionASSY'" at 44.18,-6243 h59.06
  text "'.Layer_Name'" at 1417.32,-6250 h39.37
Top Assembly:
  text "6. PLACE LABEL  ON THE LOCATION INDICATED." at -185.04,-5086.61 h118.11
  text "7." at -185.04,-5204.72 h118.11
  text "ASSEMBLY VARIANT:" at 10738.98,-5615.08 h35.43
  text "'.VariantName'" at 11300,-5615.08 h35.43
  text "DOCUMENT NUMBER:" at 12559.84,-5939.88 h45.28
  text "02-'.ProjectPCBAssyNumber'-D" at 12569.68,-6057.99 h62.99
  text "'.ProjectRevisionASSY'" at 13226.29,-6238 h59.06
  text "'.Layer_Name'" at 11841.34,-6245 h39.37
Bottom 3D Body:
  text "'.Layer_Name'" at 11841.34,-6245 h45.28
Top 3D Body:
  text "'.Layer_Name'" at 11841.34,-6245 h47.24
Bottom Courtyard:
  text ".ProjectRevisionART" at 13226.29,-6238 h59.06
  text "'.Layer_Name'" at 11841.34,-6245 h39.37
Top Courtyard:
  text "'.ProjectRevisionART'" at 13226.29,-6238 h59.06
  text "'.Layer_Name'" at 11841.34,-6245 h43.31
TITLE (M16):
  lines w3.94: 10719.29,-5565.87 13940.55,-5565.87 ; 12766.54,-5270.59 12766.54,-5388.7 13940.55,-5388.7 ; 13496.46,-6240.47 13496.46,-6190.47 ; 13496.46,-6215.47 13896.46,-6215.47 ; 13502.76,-6168.23 13502.76,-6128.86 ; 13502.76,-6148.54 13896.46,-6148.54 ; 13596.46,-6240.47 13596.46,-6190.47 ; 13696.46,-6240.47 13696.46,-6190.47 ; 13699.61,-6160.35 13699.61,-6136.73 ; 13796.46,-6240.47 13796.46,-6190.47 ; 13896.46,-6240.47 13896.46,-6190.47 ; 13896.46,-6168.23 13896.46,-6128.86 ; 13940.55,-5388.7 13940.55,-5388.7
  lines w5: -870.08,-4101.38 -670.08,-4101.38 ; -870.08,-1726.38 -670.08,-1726.38 ; -870.08,648.62 -670.08,648.62 ; 1629.92,-6476.38 1629.92,-6276.38 ; 1629.92,2823.62 1629.92,3023.62 ; 4129.92,-6476.38 4129.92,-6276.38 ; 4129.92,2823.62 4129.92,3023.62 ; 6629.92,-6476.38 6629.92,-6276.38 ; 6629.92,2823.62 6629.92,3023.62 ; 8029.92,-6276.38 9429.92,-6276.38 ; 9129.92,-6476.38 9129.92,-6276.38 ; 9129.92,2823.62 9129.92,3023.62 ; 10719.29,-6271.38 10719.29,-5270.59 ; 10719.29,-6097.36 13940.55,-6097.36 ; 10719.29,-5861.14 13940.55,-5861.14 ; 10719.29,-5624.92 13940.55,-5624.92 ; 11629.92,-6476.38 11629.92,-6276.38 ; 11629.92,2823.62 11629.92,3023.62 ; 11821.65,-6271.38 11821.65,-5624.92 ; 12530.31,-6097.36 12530.31,-5861.14 ; 13042.13,-6271.38 13042.13,-6097.36 ; 13337.4,-6271.38 13337.4,-5861.14 ; 13929.92,-5076.38 13929.92,-6276.38 ; 13929.92,-4101.38 14129.92,-4101.38 ; 13929.92,-1726.38 14129.92,-1726.38 ; 13929.92,648.62 14129.92,648.62 ; 13929.92,-6276.38 -670.08,-6276.38 -670.08,2823.62 13929.92,2823.62 13929.92,-6276.38 ; -870.08,-6476.38 14129.92,-6476.38 14129.92,3023.62 -870.08,3023.62 -870.08,-6476.38 ; 9380.71,-6271.38 13940.55,-6271.38 13940.55,-5270.59 9380.71,-5270.59 9380.71,-6271.38
  lines w10: 9579.53,2469.29 9579.53,2646.46 9579.53,2823.62 ; 10071.65,2469.29 10071.65,2646.46 10071.65,2823.62 ; 13162.21,2469.29 13162.21,2646.46 13162.21,2823.62 ; 13929.92,2646.46 9146.46,2646.46 ; 9146.46,2646.46 9146.46,2823.62 13929.92,2823.62 13929.92,2469.29 9146.46,2469.29 9146.46,2646.46
  text "1" at 361.26,2893.62 h70
  text "2" at 2856.92,2893.62 h70
  text "3" at 5346.27,2893.62 h70
  text "4" at 7852.93,2893.62 h70
  text "5" at 10351.92,2893.62 h70
  text "6" at 12856.92,2893.62 h70
  text "REV" at 9244.88,2705.51 h60
  text "ECO" at 9638.58,2705.51 h60
  text "Comments" at 11469.29,2685.83 h60
  text "Date" at 13359.06,2685.83 h60
  text "A" at -795.08,1750.62 h70
  text "A" at 14004.92,1750.62 h70
  text "B" at -795.08,-629.38 h70
  text "B" at 14004.92,-629.38 h70
  text "C" at -795.08,-3004.38 h70
  text "C" at 14004.92,-3004.38 h70
  text "PART NUMBER:" at 12805.91,-5349.33 h39.37
  text "'.ProjectpartNumber'" at 13278.35,-5359.17 h59.06
  text "TITLE:" at 10758.66,-5369.02 h45
  text "D" at -795.08,-5374.38 h70
  text "D" at 14004.92,-5374.38 h70
  text "'.ProjectTitle'" at 10758.66,-5526.5 h98.43
  text "PCB Layout Contact:" at 10758.66,-5703.66 h45.28
  text "GERBER FILE:" at 11861.02,-5703.66 h45.28
  text "'.ProjectDrawnBy'" at 10758.66,-5821.77 h62.99
  text "'.Plot_File_Name'" at 11861.02,-5821.77 h59.06
  text "M" at 9498.82,-5900.51 h600
  text "Project Owner:" at 10758.66,-5939.88 h45.28
  text "BOARD NUMBER:" at 11861.02,-5939.88 h45.28
  text "DATE:" at 13384.65,-5939.88 h45
  text "Microchip Technology Inc." at 9450.39,-6028.86 h70
  text "'.ProjectEngineer'" at 10758.66,-6057.99 h62.99
  text "04-'.ProjectPCBNumber'" at 11861.02,-6057.99 h62.99
  text "'.PRINT_DATE'" at 13384.65,-6057.99 h59.06
  text "2355 W. Chandler Blvd." at 9498.82,-6136.73 h70
  text "LAYER NAME:" at 11861.02,-6156.42 h45
  text "10mm" at 13357.09,-6160.35 h27.56
  text "PCB FILE NAME:" at 10758.66,-6166.26 h45.28
  text "REV:" at 13071.65,-6166.26 h45
  text "400mil" at 13353.15,-6227.28 h27.56
  text "Chandler, AZ  85224" at 9538.19,-6235.16 h70
  text "'.PCB_FILE_NAME_NO_PATH'" at 10758.66,-6245 h39.37
  text "1" at 361.26,-6406.38 h70
  text "2" at 2856.92,-6406.38 h70
  text "3" at 5346.27,-6406.38 h70
  text "4" at 7852.93,-6406.38 h70
  text "5" at 10351.92,-6406.38 h70
  text "6" at 12856.92,-6406.38 h70
Drill Drawing:
  circle w9.84: c-210.54,-2808.87 r32.81
  lines w9.84: -243.34,-3284.59 -210.54,-3268.18 -177.73,-3284.59 -194.13,-3251.78 -177.73,-3218.97 -210.54,-3235.37 -243.34,-3218.97 -226.94,-3251.78 -243.34,-3284.59 ; -243.34,-3136.95 -177.73,-3136.95 -177.73,-3071.33 -243.34,-3071.33 -243.34,-3136.95 ; -243.34,-2972.91 -226.94,-2972.91 -210.54,-2989.31 -194.13,-2972.91 -177.73,-2972.91 -194.13,-2956.5 -177.73,-2940.1 -194.13,-2940.1 -210.54,-2923.69 -226.94,-2940.1 -243.34,-2940.1 -226.94,-2956.5 -243.34,-2972.91 ; -243.34,-2694.04 -243.34,-2677.63 -226.94,-2661.23 -243.34,-2644.82 -243.34,-2628.42 -226.94,-2628.42 -210.54,-2644.82 -194.13,-2628.42 -177.73,-2628.42 -177.73,-2644.82 -194.13,-2661.23 -177.73,-2677.63 -177.73,-2694.04 -194.13,-2694.04 -210.54,-2677.63 -226.94,-2694.04 -243.34,-2694.04 ; -243.34,-2513.59 -210.54,-2546.4 -177.73,-2513.59 -210.54,-2480.78 -243.34,-2513.59 ; -243.34,-2333.14 -177.73,-2333.14 -210.54,-2398.76 -243.34,-2333.14
  lines w11.81: -302.19,-3328.88 7760.53,-3328.88 ; -302.19,-2295.41 7760.53,-2295.41 ; 240.01,-3476.52 240.01,-2147.78 ; 926.83,-3476.52 926.83,-2147.78 ; 2251.24,-3476.52 2251.24,-2147.78 ; 2749.15,-3476.52 2749.15,-2147.78 ; 4225.09,-3476.52 4225.09,-2147.78 ; 4805.65,-3476.52 4805.65,-2147.78 ; 5527.89,-3476.52 5527.89,-2147.78 ; 6380.02,-3476.52 6380.02,-2147.78 ; -302.19,-3476.52 7760.53,-3476.52 7760.53,-2147.78 -302.19,-2147.78 -302.19,-3476.52
  text "Symbol" at -213.61,-2251.12 h70.87
  text "Hit Count" at 284.3,-2251.12 h70.87
  text "Finished Hole Size" at 971.12,-2251.12 h70.87
  text "Plated" at 2295.53,-2251.12 h70.87
  text "Drill Layer Pair" at 2793.44,-2251.12 h70.87
  text "Via/Pad" at 4269.38,-2251.12 h70.87
  text "Hole Type" at 4849.94,-2251.12 h70.87
  text "Hole Length" at 5572.18,-2251.12 h70.87
  text "Routed Path Length" at 6424.31,-2251.12 h70.87
  text "2" at 284.3,-2398.76 h59.06
  text "0.300mm (11.81mil)" at 971.12,-2398.76 h59.06
  text "PTH" at 2295.53,-2398.76 h59.06
  text "Top Layer - Bottom Layer" at 2793.44,-2398.76 h59.06
  text "Via" at 4269.38,-2398.76 h59.06
  text "Round" at 4849.94,-2398.76 h59.06
  text "-" at 5572.18,-2398.76 h59.06
  text "-" at 6424.31,-2398.76 h59.06
  text "2" at 284.3,-2546.4 h59.06
  text "1.000mm (39.37mil)" at 971.12,-2546.4 h59.06
  text "NPTH" at 2295.53,-2546.4 h59.06
  text "Top Layer - Bottom Layer" at 2793.44,-2546.4 h59.06
  text "Pad" at 4269.38,-2546.4 h59.06
  text "Round" at 4849.94,-2546.4 h59.06
  text "-" at 5572.18,-2546.4 h59.06
  text "-" at 6424.31,-2546.4 h59.06
  text "2" at 284.3,-2694.04 h59.06
  text "1.200mm (47.24mil)" at 971.12,-2694.04 h59.06
  text "PTH" at 2295.53,-2694.04 h59.06
  text "Top Layer - Bottom Layer" at 2793.44,-2694.04 h59.06
  text "Pad" at 4269.38,-2694.04 h59.06
  text "Round" at 4849.94,-2694.04 h59.06
  text "-" at 5572.18,-2694.04 h59.06
  text "-" at 6424.31,-2694.04 h59.06
  text "6" at 284.3,-2841.67 h59.06
  text "0.991mm (39.00mil)" at 971.12,-2841.67 h59.06
  text "PTH" at 2295.53,-2841.67 h59.06
  text "Top Layer - Bottom Layer" at 2793.44,-2841.67 h59.06
  text "Pad" at 4269.38,-2841.67 h59.06
  text "Round" at 4849.94,-2841.67 h59.06
  text "-" at 5572.18,-2841.67 h59.06
  text "-" at 6424.31,-2841.67 h59.06
  text "10" at 284.3,-2989.31 h59.06
  text "0.900mm (35.43mil)" at 971.12,-2989.31 h59.06
  text "PTH" at 2295.53,-2989.31 h59.06
  text "Top Layer - Bottom Layer" at 2793.44,-2989.31 h59.06
  text "Pad" at 4269.38,-2989.31 h59.06
  text "Round" at 4849.94,-2989.31 h59.06
  text "-" at 5572.18,-2989.31 h59.06
  text "-" at 6424.31,-2989.31 h59.06
  text "16" at 284.3,-3136.95 h59.06
  text "0.889mm (35.00mil)" at 971.12,-3136.95 h59.06
  text "PTH" at 2295.53,-3136.95 h59.06
  text "Top Layer - Bottom Layer" at 2793.44,-3136.95 h59.06
  text "Pad" at 4269.38,-3136.95 h59.06
  text "Round" at 4849.94,-3136.95 h59.06
  text "-" at 5572.18,-3136.95 h59.06
  text "-" at 6424.31,-3136.95 h59.06
  text "28" at 284.3,-3284.59 h59.06
  text "0.400mm (15.75mil)" at 971.12,-3284.59 h59.06
  text "PTH" at 2295.53,-3284.59 h59.06
  text "Top Layer - Bottom Layer" at 2793.44,-3284.59 h59.06
  text "Via" at 4269.38,-3284.59 h59.06
  text "Round" at 4849.94,-3284.59 h59.06
  text "-" at 5572.18,-3284.59 h59.06
  text "-" at 6424.31,-3284.59 h59.06
  text "66 Total" at 284.3,-3432.22 h59.06
  text "DOCUMENT NUMBER:" at 12559.84,-5939.88 h45.28
  text "04-'.ProjectPCBNumber'-D" at 12569.68,-6057.99 h62.99
  text "'.ProjectRevisionFAB'" at 13226.29,-6238 h59.06
TITLE MIRROR (M17):
  lines w3.94: -625.98,-6245.47 -625.98,-6195.47 ; -625.98,-6220.47 -225.98,-6220.47 ; -625.98,-6173.23 -625.98,-6133.86 ; -625.98,-6153.54 -232.28,-6153.54 ; -525.98,-6245.47 -525.98,-6195.47 ; -429.13,-6165.35 -429.13,-6141.73 ; -425.98,-6245.47 -425.98,-6195.47 ; -325.98,-6245.47 -325.98,-6195.47 ; -232.28,-6173.23 -232.28,-6133.86 ; -225.98,-6245.47 -225.98,-6195.47
  lines w5: -870.08,-4101.38 -670.08,-4101.38 ; -870.08,-1726.38 -670.08,-1726.38 ; -870.08,648.62 -670.08,648.62 ; -670.08,-6102.36 2551.18,-6102.36 ; -670.08,-5866.14 2551.18,-5866.14 ; -669.29,-5629.92 2551.97,-5629.92 ; -669.29,-5570.87 2551.97,-5570.87 ; -669.29,-5393.7 -645,-5393.7 ; -66.93,-6276.38 -66.93,-5866.14 ; 228.35,-6276.38 228.35,-6102.36 ; 504.72,-5275.59 504.72,-5393.7 -645,-5393.7 ; 740.16,-6102.36 740.16,-5866.14 ; 1449.61,-6276.38 1449.61,-5629.92 ; 1629.92,-6476.38 1629.92,-6276.38 ; 1629.92,2823.62 1629.92,3023.62 ; 2551.97,-6276.38 2551.97,-5275.59 ; 4129.92,-6476.38 4129.92,-6276.38 ; 4129.92,2823.62 4129.92,3023.62 ; 6629.92,-6476.38 6629.92,-6276.38 ; 6629.92,2823.62 6629.92,3023.62 ; 9129.92,-6476.38 9129.92,-6276.38 ; 9129.92,2823.62 9129.92,3023.62 ; 11629.92,-6476.38 11629.92,-6276.38 ; 11629.92,2823.62 11629.92,3023.62 ; 13929.92,-4101.38 14129.92,-4101.38 ; 13929.92,-1726.38 14129.92,-1726.38 ; 13929.92,648.62 14129.92,648.62 ; -670.08,-6276.38 3890.55,-6276.38 3890.55,-5275.59 -670.08,-5275.59 -670.08,-6276.38 ; -670.08,-6276.38 -670.08,2823.62 13929.92,2823.62 13929.92,-6276.38 -670.08,-6276.38 ; -645,-5393.7 -645,-5393.7 ; -870.08,-6476.38 -870.08,3023.62 14129.92,3023.62 14129.92,-6476.38 -870.08,-6476.38
  text "6" at 402.92,2893.62 h70
  text "5" at 2907.92,2893.62 h70
  text "4" at 5406.91,2893.62 h70
  text "3" at 7913.58,2893.62 h70
  text "2" at 10402.92,2893.62 h70
  text "1" at 12898.58,2893.62 h70
  text "A" at -745.08,1750.62 h70
  text "A" at 14054.92,1750.62 h70
  text "B" at -745.08,-629.38 h70
  text "B" at 14054.92,-629.38 h70
  text "C" at -745.08,-3004.38 h70
  text "C" at 14054.92,-3004.38 h70
  text "PART NUMBER:" at 465.35,-5354.33 h39.37
  text "TITLE:" at 2512.6,-5354.33 h45
  text "'.ProjectpartNumber'" at -7.09,-5364.17 h59.06
  text "D" at -745.08,-5374.38 h70
  text "D" at 14054.92,-5374.38 h70
  text "'.ProjectTitle'" at 2512.6,-5531.5 h98.43
  text "GERBER FILE:" at 1410.24,-5708.66 h45
  text "PCB DESIGNER:" at 2512.6,-5708.66 h45
  text "'.Plot_File_Name'" at 1410.24,-5826.77 h59.06
  text "'.ProjectDrawnBy'" at 2512.6,-5826.77 h70
  text "M" at 3772.44,-5905.51 h600
  text "DATE:" at -114.17,-5944.88 h45
  text "BOARD NUMBER:" at 1409.45,-5944.88 h45
  text "ENGINEER:" at 2511.81,-5944.88 h45
  text "Microchip Technology Inc." at 3820.87,-6033.86 h70
  text "'.PRINT_DATE'" at -114.17,-6062.99 h59.06
  text "04-'.ProjectPCBNumber'" at 1409.45,-6062.99 h62.99
  text "'.ProjectEngineer'" at 2511.81,-6062.99 h70
  text "2355 W. Chandler Blvd." at 3772.44,-6141.73 h70
  text "LAYER NAME:" at 1409.45,-6161.42 h45
  text "10mm" at -86.61,-6165.35 h27.56
  text "REV:" at 198.82,-6171.26 h45
  text "PCB FILE NAME:" at 2511.81,-6171.26 h45
  text "400mil" at -82.68,-6232.28 h27.56
  text "Chandler, AZ  85224" at 3733.07,-6240.16 h70
  text "'.PCB_FILE_NAME_NO_PATH'" at 2511.81,-6250 h45
  text "6" at 402.92,-6406.38 h70
  text "5" at 2907.92,-6406.38 h70
  text "4" at 5406.91,-6406.38 h70
  text "3" at 7913.58,-6406.38 h70
  text "2" at 10402.92,-6406.38 h70
  text "1" at 12898.58,-6406.38 h70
